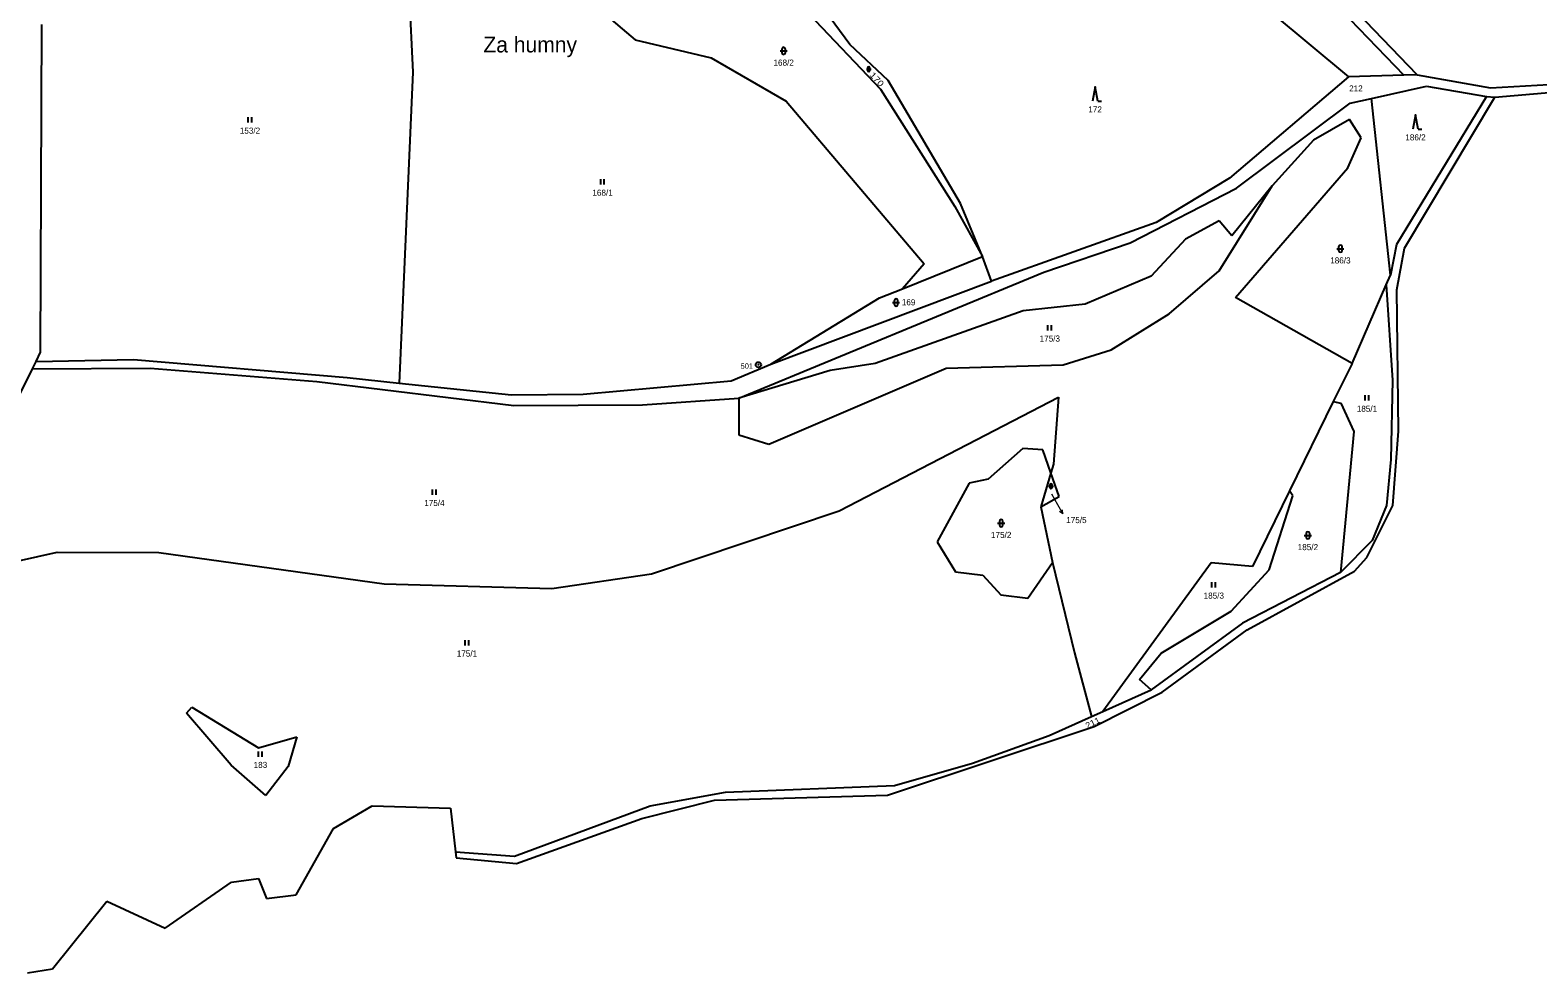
# Model space of a CAD drawing. Extents: x -601877 to -599786, y -1122905 to -1121218.
# Drawn here: x -600627.6 to -600206.4, y -1122698.3 to -1122435.1 of the extents above; entities that cross this region are included whole.
import ezdxf
from ezdxf.enums import TextEntityAlignment as Align

# ---------------------------------------------------------------- set-up
doc = ezdxf.new("R2010")
doc.units = 0
doc.header["$LTSCALE"] = 0.68
for name, color, linetype, lineweight in [('1', 7, 'Continuous', 25), ('3', 7, 'Continuous', 25), ('7', 7, 'Continuous', 13), ('8', 7, 'Continuous', 25)]:
    doc.layers.add(name, color=color, linetype=linetype, lineweight=lineweight)
doc.layers.add('2', color=7, linetype='Continuous')

msp = doc.modelspace()

# ---------------------------------------------------------------- linework, layer by layer
at = {"layer": '1'}
for p, q in [((-600523.24, -1122393.43), (-600520.71, -1122446.81)), ((-600467.69, -1122430.08), (-600458.56, -1122437.79)), ((-600410.09, -1122430.52), (-600390.04, -1122451.6)), ((-600398.64, -1122439.15), (-600405.72, -1122429.56)), ((-600280.89, -1122430.24), (-600259.28, -1122448.16)), ((-600258.93, -1122432.06), (-600243.87, -1122447.69)), ((-600240.16, -1122447.58), (-600256.85, -1122430.19)), ((-600624.7, -1122525.05), (-600624.36, -1122433.54)), ((-600458.56, -1122437.79), (-600437.34, -1122442.85)), ((-600387.94, -1122449.2), (-600398.64, -1122439.15)), ((-600437.34, -1122442.85), (-600416.44, -1122454.96)), ((-600520.71, -1122446.81), (-600524.49, -1122533.65)), ((-600367.73, -1122483.5), (-600387.94, -1122449.2)), ((-600259.28, -1122448.16), (-600292.6, -1122476.49)), ((-600243.87, -1122447.69), (-600259.28, -1122448.16)), ((-600240.16, -1122447.58), (-600243.87, -1122447.69)), ((-600240.16, -1122447.58), (-600219.61, -1122451.24)), ((-600390.04, -1122451.6), (-600369.25, -1122484.4)), ((-600252.87, -1122454.16), (-600237.51, -1122450.75)), ((-600220.77, -1122453.64), (-600245.92, -1122494.95)), ((-600237.51, -1122450.75), (-600220.77, -1122453.64)), ((-600220.77, -1122453.64), (-600218.47, -1122453.82)), ((-600219.61, -1122451.24), (-600192.78, -1122449.7)), ((-600218.47, -1122453.82), (-600193.84, -1122451.72)), ((-600416.44, -1122454.96), (-600377.83, -1122500.41)), ((-600290.61, -1122479.28), (-600258.84, -1122455.48)), ((-600258.84, -1122455.48), (-600252.87, -1122454.16)), ((-600247.57, -1122503.51), (-600252.87, -1122454.16)), ((-600243.69, -1122496.03), (-600218.47, -1122453.82)), ((-600259.04, -1122460.1), (-600269.05, -1122465.88)), ((-600255.75, -1122465.16), (-600259.04, -1122460.1)), ((-600269.05, -1122465.88), (-600280.66, -1122478.62)), ((-600259.48, -1122473.53), (-600255.75, -1122465.16)), ((-600290.89, -1122509.79), (-600259.48, -1122473.53)), ((-600292.6, -1122476.49), (-600313.06, -1122488.79)), ((-600295.45, -1122502.28), (-600280.66, -1122478.62)), ((-600280.66, -1122478.62), (-600291.93, -1122492.57)), ((-600320.31, -1122494.47), (-600290.61, -1122479.28)), ((-600369.25, -1122484.4), (-600361.53, -1122498.33)), ((-600361.53, -1122498.33), (-600367.73, -1122483.5)), ((-600313.06, -1122488.79), (-600359.07, -1122505.19)), ((-600295.45, -1122488.39), (-600304.86, -1122493.51)), ((-600291.93, -1122492.57), (-600295.45, -1122488.39)), ((-600344.4, -1122502.72), (-600320.31, -1122494.47)), ((-600304.86, -1122493.51), (-600314.48, -1122503.85)), ((-600245.92, -1122494.95), (-600247.57, -1122503.51)), ((-600383.92, -1122507.3), (-600361.53, -1122498.33)), ((-600359.07, -1122505.19), (-600361.53, -1122498.33)), ((-600245.81, -1122507.66), (-600243.69, -1122496.03)), ((-600429.64, -1122537.83), (-600344.4, -1122502.72)), ((-600377.83, -1122500.41), (-600383.92, -1122507.3)), ((-600314.48, -1122503.85), (-600332.9, -1122511.67)), ((-600309.42, -1122514.28), (-600295.45, -1122502.28)), ((-600248.77, -1122506.27), (-600247.57, -1122503.51)), ((-600420.73, -1122528.37), (-600359.07, -1122505.19)), ((-600390.37, -1122509.88), (-600383.92, -1122507.3)), ((-600258.33, -1122528.15), (-600248.77, -1122506.27)), ((-600248.77, -1122506.27), (-600247.06, -1122532.85)), ((-600245.32, -1122547.12), (-600245.81, -1122507.66)), ((-600420.73, -1122528.37), (-600390.37, -1122509.88)), ((-600332.9, -1122511.67), (-600350.17, -1122513.48)), ((-600258.33, -1122528.15), (-600290.89, -1122509.79)), ((-600350.17, -1122513.48), (-600391.53, -1122528.23)), ((-600325.59, -1122524.41), (-600309.42, -1122514.28)), ((-600625.96, -1122527.62), (-600624.7, -1122525.05)), ((-600339.01, -1122528.59), (-600325.59, -1122524.41)), ((-600626.99, -1122529.72), (-600625.96, -1122527.62)), ((-600626.99, -1122529.72), (-600594.07, -1122529.47)), ((-600625.96, -1122527.62), (-600598.69, -1122527.05)), ((-600598.69, -1122527.05), (-600539.08, -1122532.11)), ((-600594.07, -1122529.47), (-600547.55, -1122533.21)), ((-600431.73, -1122532.99), (-600420.73, -1122528.37)), ((-600421.28, -1122550.71), (-600371.67, -1122529.47)), ((-600391.53, -1122528.23), (-600404.07, -1122530.1)), ((-600371.67, -1122529.47), (-600339.01, -1122528.59)), ((-600258.33, -1122528.15), (-600263.55, -1122538.78)), ((-600634.46, -1122544.94), (-600626.99, -1122529.72)), ((-600547.55, -1122533.21), (-600492.44, -1122539.92)), ((-600539.08, -1122532.11), (-600524.49, -1122533.65)), ((-600524.49, -1122533.65), (-600493.1, -1122536.95)), ((-600473.08, -1122536.73), (-600431.73, -1122532.99)), ((-600404.07, -1122530.1), (-600429.64, -1122537.83)), ((-600247.06, -1122532.85), (-600247.44, -1122555.03)), ((-600493.1, -1122536.95), (-600473.08, -1122536.73)), ((-600456.58, -1122539.7), (-600429.64, -1122537.83)), ((-600429.64, -1122537.83), (-600429.64, -1122548.07)), ((-600401.59, -1122569.31), (-600340.33, -1122537.61)), ((-600340.33, -1122537.61), (-600341.76, -1122556.32)), ((-600492.44, -1122539.92), (-600456.58, -1122539.7)), ((-600263.55, -1122538.78), (-600275.8, -1122563.73)), ((-600263.55, -1122538.78), (-600261.41, -1122539.26)), ((-600261.41, -1122539.26), (-600257.78, -1122547.19)), ((-600429.64, -1122548.07), (-600421.28, -1122550.71)), ((-600257.78, -1122547.19), (-600261.57, -1122586.56)), ((-600246.92, -1122567.79), (-600245.32, -1122547.12)), ((-600350.28, -1122551.92), (-600359.96, -1122560.51)), ((-600344.67, -1122552.25), (-600350.28, -1122551.92)), ((-600342.46, -1122558.68), (-600344.67, -1122552.25)), ((-600342.46, -1122558.68), (-600345.28, -1122568.21)), ((-600341.76, -1122556.32), (-600342.46, -1122558.68)), ((-600340.16, -1122565.35), (-600342.46, -1122558.68)), ((-600247.44, -1122555.03), (-600248.65, -1122567.8)), ((-600365.24, -1122561.61), (-600374.26, -1122578.01)), ((-600359.96, -1122560.51), (-600365.24, -1122561.61)), ((-600345.28, -1122568.21), (-600340.16, -1122565.35)), ((-600275.8, -1122563.73), (-600286.16, -1122584.83)), ((-600281.43, -1122585.82), (-600274.83, -1122565.13)), ((-600274.83, -1122565.13), (-600275.8, -1122563.73)), ((-600454.06, -1122586.92), (-600401.59, -1122569.31)), ((-600345.28, -1122568.21), (-600342.03, -1122583.78)), ((-600254.15, -1122582.35), (-600246.92, -1122567.79)), ((-600248.65, -1122567.8), (-600252.72, -1122577.59)), ((-600374.26, -1122578.01), (-600369.09, -1122586.37)), ((-600252.72, -1122577.59), (-600261.57, -1122586.56)), ((-600640.71, -1122585.49), (-600620.03, -1122580.87)), ((-600620.03, -1122580.87), (-600591.65, -1122580.98)), ((-600591.65, -1122580.98), (-600528.74, -1122589.67)), ((-600348.85, -1122593.75), (-600342.03, -1122583.78)), ((-600342.03, -1122583.78), (-600335.82, -1122608.93)), ((-600297.71, -1122583.84), (-600327.92, -1122625.33)), ((-600286.16, -1122584.83), (-600297.71, -1122583.84)), ((-600257.66, -1122586.14), (-600254.15, -1122582.35)), ((-600481.88, -1122590.99), (-600454.06, -1122586.92)), ((-600369.09, -1122586.37), (-600361.5, -1122587.25)), ((-600361.5, -1122587.25), (-600356.44, -1122592.75)), ((-600292.1, -1122597.38), (-600281.43, -1122585.82)), ((-600261.57, -1122586.56), (-600288.91, -1122600.68)), ((-600287.61, -1122602.58), (-600257.66, -1122586.14)), ((-600528.74, -1122589.67), (-600481.88, -1122590.99)), ((-600356.44, -1122592.75), (-600348.85, -1122593.75)), ((-600288.91, -1122600.68), (-600314.42, -1122619.28)), ((-600311.67, -1122609.04), (-600292.1, -1122597.38)), ((-600311.41, -1122619.96), (-600287.61, -1122602.58)), ((-600335.82, -1122608.93), (-600331.11, -1122626.76)), ((-600317.72, -1122616.42), (-600311.67, -1122609.04)), ((-600314.42, -1122619.28), (-600317.72, -1122616.42)), ((-600330.38, -1122629.52), (-600311.41, -1122619.96)), ((-600327.92, -1122625.33), (-600314.42, -1122619.28)), ((-600583.9, -1122625.77), (-600582.47, -1122624.18)), ((-600571.41, -1122640.3), (-600583.9, -1122625.77)), ((-600582.47, -1122624.18), (-600563.82, -1122635.46)), ((-600331.11, -1122626.76), (-600327.92, -1122625.33)), ((-600388.09, -1122648.71), (-600330.38, -1122629.52)), ((-600342.91, -1122632.05), (-600331.11, -1122626.76)), ((-600563.82, -1122635.46), (-600553.1, -1122632.38)), ((-600553.1, -1122632.38), (-600555.52, -1122640.74)), ((-600364.36, -1122639.75), (-600342.91, -1122632.05)), ((-600561.73, -1122648.78), (-600571.41, -1122640.3)), ((-600555.52, -1122640.74), (-600561.73, -1122648.78)), ((-600386.14, -1122646.03), (-600364.36, -1122639.75)), ((-600433.32, -1122647.9), (-600386.14, -1122646.03)), ((-600542.83, -1122658.06), (-600532.07, -1122651.67)), ((-600532.07, -1122651.67), (-600510.17, -1122652.31)), ((-600492.28, -1122665.73), (-600454.44, -1122651.64)), ((-600456.69, -1122655.2), (-600436.43, -1122650.12)), ((-600454.44, -1122651.64), (-600433.32, -1122647.9)), ((-600436.43, -1122650.12), (-600388.09, -1122648.71)), ((-600510.17, -1122652.31), (-600508.82, -1122664.56)), ((-600491.78, -1122667.75), (-600456.69, -1122655.2)), ((-600553.3, -1122676.57), (-600542.83, -1122658.06)), ((-600508.82, -1122664.56), (-600492.28, -1122665.73)), ((-600508.82, -1122664.56), (-600508.63, -1122666.18)), ((-600508.63, -1122666.18), (-600491.78, -1122667.75)), ((-600571.36, -1122673.03), (-600563.83, -1122671.96)), ((-600563.83, -1122671.96), (-600561.55, -1122677.58)), ((-600589.84, -1122685.84), (-600571.36, -1122673.03)), ((-600561.55, -1122677.58), (-600553.3, -1122676.57)), ((-600621.34, -1122697.21), (-600606.21, -1122678.31)), ((-600606.21, -1122678.31), (-600589.84, -1122685.84)), ((-600628.34, -1122698.31), (-600621.34, -1122697.21))]:
    msp.add_line(p, q, dxfattribs=at)
at = {"layer": '3'}
for p, q in [((-600418.101, -1122440.911), (-600416.099, -1122440.911)), ((-600417.601, -1122440.411), (-600417.601, -1122441.412)), ((-600416.599, -1122441.412), (-600416.599, -1122440.411)), ((-600394.001, -1122446.041), (-600392.659, -1122446.041)), ((-600393.665, -1122445.705), (-600393.665, -1122446.376)), ((-600392.995, -1122446.376), (-600392.995, -1122445.705)), ((-600329.35, -1122454.98), (-600328.354, -1122454.98)), ((-600566.701, -1122460.9), (-600566.701, -1122459.4)), ((-600565.7, -1122460.9), (-600565.7, -1122459.4)), ((-600239.84, -1122462.78), (-600238.844, -1122462.78)), ((-600468.201, -1122478.23), (-600468.201, -1122476.73)), ((-600467.2, -1122478.23), (-600467.2, -1122476.73)), ((-600262.071, -1122495.631), (-600262.071, -1122496.632)), ((-600261.069, -1122496.632), (-600261.069, -1122495.631)), ((-600262.571, -1122496.131), (-600260.569, -1122496.131)), ((-600386.701, -1122511.161), (-600384.699, -1122511.161)), ((-600386.201, -1122510.661), (-600386.201, -1122511.662)), ((-600385.199, -1122511.662), (-600385.199, -1122510.661)), ((-600343.261, -1122518.95), (-600343.261, -1122517.45)), ((-600342.26, -1122518.95), (-600342.26, -1122517.45)), ((-600254.661, -1122538.55), (-600254.661, -1122537.05)), ((-600253.66, -1122538.55), (-600253.66, -1122537.05)), ((-600343.091, -1122562.471), (-600341.749, -1122562.471)), ((-600342.755, -1122562.135), (-600342.755, -1122562.806)), ((-600342.085, -1122562.806), (-600342.085, -1122562.135)), ((-600515.171, -1122564.85), (-600515.171, -1122563.35)), ((-600514.17, -1122564.85), (-600514.17, -1122563.35)), ((-600357.331, -1122572.771), (-600355.329, -1122572.771)), ((-600356.831, -1122572.271), (-600356.831, -1122573.272)), ((-600355.829, -1122573.272), (-600355.829, -1122572.271)), ((-600271.151, -1122575.681), (-600271.151, -1122576.682)), ((-600270.149, -1122576.682), (-600270.149, -1122575.681)), ((-600271.651, -1122576.181), (-600269.649, -1122576.181)), ((-600297.451, -1122590.72), (-600297.451, -1122589.22)), ((-600296.45, -1122590.72), (-600296.45, -1122589.22)), ((-600506.091, -1122606.89), (-600506.091, -1122605.39)), ((-600505.09, -1122606.89), (-600505.09, -1122605.39)), ((-600563.781, -1122637.99), (-600563.781, -1122636.49)), ((-600562.78, -1122637.99), (-600562.78, -1122636.49))]:
    msp.add_line(p, q, dxfattribs=at)
for points in [[(-600329.35, -1122454.98), (-600330.1, -1122450.98), (-600330.85, -1122454.98)], [(-600239.84, -1122462.78), (-600240.59, -1122458.78), (-600241.34, -1122462.78)]]:
    msp.add_lwpolyline(points, dxfattribs=at)
for centre, radius, start, end in [((-600417.1, -1122440.4109), 0.5, 0, 180), ((-600417.1, -1122441.4109), 0.5, 180, 359.98789), ((-600393.33, -1122445.7056), 0.335, 0, 180), ((-600393.33, -1122446.3756), 0.335, 180, 359.98789), ((-600261.57, -1122495.6309), 0.5, 0, 180), ((-600261.57, -1122496.6309), 0.5, 180, 359.98789), ((-600385.7, -1122510.6609), 0.5, 0, 180), ((-600385.7, -1122511.6609), 0.5, 180, 359.98789), ((-600342.42, -1122562.1356), 0.335, 0, 180), ((-600342.42, -1122562.8056), 0.335, 180, 359.98789), ((-600356.33, -1122572.2709), 0.5, 0, 180), ((-600356.33, -1122573.2709), 0.5, 180, 359.98789), ((-600270.65, -1122575.6809), 0.5, 0, 180), ((-600270.65, -1122576.6809), 0.5, 180, 359.98789)]:
    msp.add_arc(centre, radius, start, end, dxfattribs=at)
at = {"layer": '7'}
msp.add_line((-600339.155, -1122570.185), (-600339.203, -1122569.066), dxfattribs=at)
msp.add_lwpolyline([(-600342.25, -1122564.58), (-600340.61, -1122567.56), (-600339.155, -1122570.185), (-600340.079, -1122569.552)], dxfattribs=at)
at = {"layer": '8'}
for radius in [0.75, 0.03]:
    msp.add_circle((-600424.17, -1122528.5398), radius, dxfattribs=at)

# ---------------------------------------------------------------- texts
at = {"layer": '2'}
for s, p in [('168/2', (-600417.1, -1122445.035)), ('212', (-600257.229, -1122452.245)), ('172', (-600330.099, -1122458.105)), ('153/2', (-600566.19, -1122464.025)), ('186/2', (-600240.59, -1122465.905)), ('168/1', (-600467.69, -1122481.355)), ('186/3', (-600261.57, -1122500.255)), ('175/3', (-600342.75, -1122522.075)), ('185/1', (-600254.15, -1122541.675)), ('175/4', (-600514.66, -1122567.975)), ('175/2', (-600356.33, -1122576.895)), ('185/2', (-600270.65, -1122580.305)), ('185/3', (-600296.94, -1122593.845)), ('175/1', (-600505.58, -1122610.015)), ('183', (-600563.269, -1122641.115))]:
    msp.add_text(s, height=1.7, dxfattribs=at).set_placement(p, align=Align.CENTER)
for s, rotation, width, p in [('170', 312, 1.2, (-600391.695, -1122449.4237)), ('211', 26, 1.1, (-600330.3936, -1122629.2685))]:
    msp.add_text(s, height=1.7, rotation=rotation, dxfattribs=dict(at, width=width)).set_placement(p, align=Align.CENTER)
msp.add_text('169', height=1.7, rotation=359, dxfattribs=at).set_placement((-600382.2098, -1122511.9341), align=Align.CENTER)
msp.add_text('175/5', height=1.7, dxfattribs=at).set_placement((-600338.17, -1122572.755))
at = {"layer": '7'}
msp.add_text('Za humny', height=4.4, dxfattribs=at).set_placement((-600487.909, -1122441.35), align=Align.CENTER)
at = {"layer": '8'}
msp.add_text('501', height=1.5, dxfattribs=at).set_placement((-600425.669, -1122529.657), align=Align.RIGHT)

doc.saveas('drawing.dxf')
